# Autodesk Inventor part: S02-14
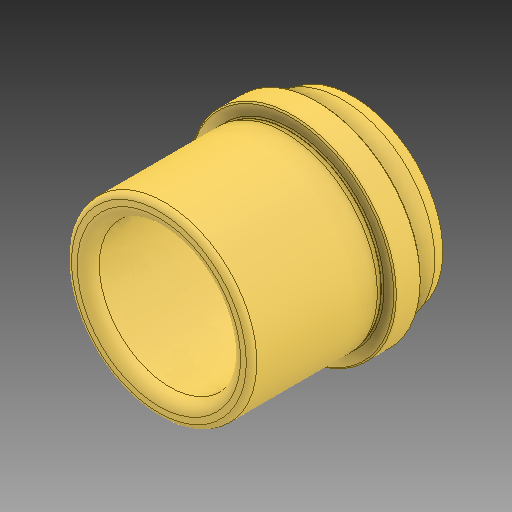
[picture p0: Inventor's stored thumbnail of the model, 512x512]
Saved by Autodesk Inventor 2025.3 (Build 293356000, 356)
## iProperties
Created: 2025-04
Part Number: S02-14
Material: Všeobecné
Document SubType Name: Modeling
Designer: Patrik
Density: 1 g/cm^3
Appearance: Výchozí
Description: Vodící pouzdro s nákružkem bezúdržbové
Stock Number: E 1105/32-36
User Status: 2.0598
Author: Patrik
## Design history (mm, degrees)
feature "Base1"
node "Těleso1"
